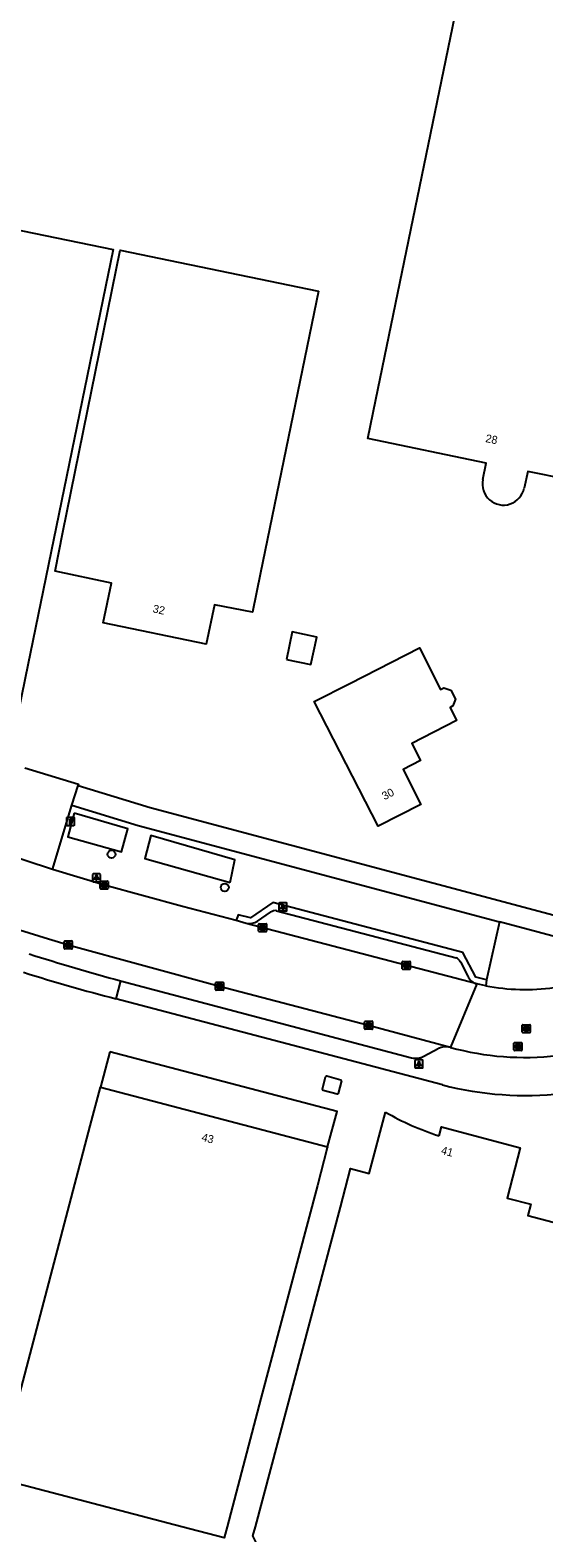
# Model space of a CAD drawing. Extents: x 157692 to 159670, y 381454 to 383289.
# Drawn here: x 158202.3 to 158266.5, y 381749.2 to 381937.1 of the extents above; entities that cross this region are included whole.
import ezdxf

# ---------------------------------------------------------------- set-up
doc = ezdxf.new("R2010")
doc.units = 0
for name, color, linetype in [('IMGEO_Boom', 7, 'Continuous'), ('IMGEO_Groenvoorziening', 7, 'Continuous'), ('IMGEO_Kolk', 7, 'Continuous'), ('IMGEO_Lichtpunt', 7, 'Continuous'), ('IMGEO_Paal', 7, 'Continuous'), ('IMGEO_Pand', 7, 'Continuous'), ('IMGEO_Pand_nummerreeks', 7, 'Continuous'), ('IMGEO_Pand_overbouw', 7, 'Continuous'), ('IMGEO_Rijbaan_lokaal_gesloten', 7, 'Continuous'), ('IMGEO_Rijbaan_lokaal_open', 7, 'Continuous'), ('IMGEO_Rioolput', 7, 'Continuous'), ('IMGEO_Voetpad_open', 7, 'Continuous'), ('IMGEO_Waterloop', 7, 'Continuous')]:
    doc.layers.add(name, color=color, linetype=linetype)

msp = doc.modelspace()

# ---------------------------------------------------------------- linework, layer by layer
at = {"layer": 'IMGEO_Boom'}
for centre in [(158212.48, 381834.06), (158226.62, 381829.91)]:
    msp.add_circle(centre, 0.489, dxfattribs=at)
at = {"layer": 'IMGEO_Groenvoorziening'}
msp.add_lwpolyline([(158260.95, 381825.62), (158259.32, 381818.38)], dxfattribs=at)
at = {"layer": 'IMGEO_Kolk'}
for p, q in [((158211.06, 381829.78), (158211.06, 381830.63)), ((158211.13, 381830.7), (158211.99, 381830.7)), ((158211.55, 381830.48), (158211.57, 381830.48)), ((158212.06, 381830.63), (158212.06, 381829.78)), ((158211.99, 381829.7), (158211.13, 381829.7)), ((158211.57, 381829.92), (158211.54, 381829.92)), ((158230.85, 381824.44), (158230.85, 381825.29)), ((158230.93, 381825.37), (158231.78, 381825.37)), ((158231.34, 381825.15), (158231.36, 381825.15)), ((158231.36, 381824.59), (158231.34, 381824.59)), ((158231.85, 381825.29), (158231.85, 381824.44)), ((158206.57, 381822.3), (158206.57, 381823.15)), ((158206.64, 381823.22), (158207.49, 381823.22)), ((158207.05, 381823), (158207.08, 381823)), ((158207.57, 381823.15), (158207.57, 381822.3)), ((158231.78, 381824.37), (158230.93, 381824.37)), ((158207.49, 381822.22), (158206.64, 381822.22)), ((158207.08, 381822.44), (158207.05, 381822.44)), ((158248.79, 381819.73), (158248.79, 381820.59)), ((158248.87, 381820.66), (158249.72, 381820.66)), ((158249.72, 381819.66), (158248.87, 381819.66)), ((158249.28, 381820.44), (158249.31, 381820.44)), ((158249.3, 381819.88), (158249.28, 381819.88)), ((158249.79, 381820.59), (158249.79, 381819.73)), ((158225.47, 381817.14), (158225.47, 381817.99)), ((158225.55, 381818.06), (158226.4, 381818.06)), ((158226.4, 381817.06), (158225.55, 381817.06)), ((158225.96, 381817.84), (158225.99, 381817.84)), ((158225.98, 381817.28), (158225.96, 381817.28)), ((158226.47, 381817.99), (158226.47, 381817.14)), ((158244.08, 381812.26), (158244.08, 381813.11)), ((158244.15, 381813.19), (158245, 381813.19)), ((158245, 381812.18), (158244.15, 381812.18)), ((158244.59, 381812.41), (158244.56, 381812.41)), ((158244.57, 381812.96), (158244.59, 381812.96)), ((158245.08, 381813.11), (158245.08, 381812.26))]:
    msp.add_line(p, q, dxfattribs=at)
for points in [[(158211.06, 381829.78), (158211.06, 381830.63)], [(158211.13, 381830.7), (158211.99, 381830.7)], [(158211.38, 381830.4), (158211.5, 381830.4), (158211.5, 381830.25), (158211.63, 381830.4), (158211.8, 381830.4), (158211.65, 381830.25), (158211.8, 381830), (158211.65, 381830), (158211.57, 381830.17), (158211.5, 381830.1), (158211.5, 381830), (158211.38, 381830), (158211.38, 381830.4)], [(158212.06, 381830.63), (158212.06, 381829.78)], [(158211.99, 381829.7), (158211.13, 381829.7)], [(158230.85, 381824.44), (158230.85, 381825.29)], [(158230.93, 381825.37), (158231.78, 381825.37)], [(158231.17, 381825.07), (158231.3, 381825.07), (158231.3, 381824.92), (158231.42, 381825.07), (158231.59, 381825.07), (158231.44, 381824.92), (158231.6, 381824.67), (158231.44, 381824.67), (158231.36, 381824.83), (158231.3, 381824.77), (158231.3, 381824.67), (158231.17, 381824.67), (158231.17, 381825.07)], [(158231.85, 381825.29), (158231.85, 381824.44)], [(158206.57, 381822.3), (158206.57, 381823.15)], [(158206.64, 381823.22), (158207.49, 381823.22)], [(158206.89, 381822.92), (158207.01, 381822.92), (158207.01, 381822.77), (158207.14, 381822.92), (158207.3, 381822.92), (158207.16, 381822.77), (158207.31, 381822.52), (158207.16, 381822.52), (158207.07, 381822.69), (158207.01, 381822.62), (158207.01, 381822.52), (158206.89, 381822.52), (158206.89, 381822.92)], [(158207.57, 381823.15), (158207.57, 381822.3)], [(158231.78, 381824.37), (158230.93, 381824.37)], [(158207.49, 381822.22), (158206.64, 381822.22)], [(158248.79, 381819.73), (158248.79, 381820.59)], [(158248.87, 381820.66), (158249.72, 381820.66)], [(158249.72, 381819.66), (158248.87, 381819.66)], [(158249.11, 381820.36), (158249.24, 381820.36), (158249.24, 381820.21), (158249.37, 381820.36), (158249.53, 381820.36), (158249.38, 381820.21), (158249.54, 381819.96), (158249.38, 381819.96), (158249.3, 381820.12), (158249.24, 381820.06), (158249.24, 381819.96), (158249.11, 381819.96), (158249.11, 381820.36)], [(158249.79, 381820.59), (158249.79, 381819.73)], [(158225.47, 381817.14), (158225.47, 381817.99)], [(158225.55, 381818.06), (158226.4, 381818.06)], [(158226.4, 381817.06), (158225.55, 381817.06)], [(158225.79, 381817.76), (158225.92, 381817.76), (158225.92, 381817.61), (158226.05, 381817.76), (158226.21, 381817.76), (158226.07, 381817.61), (158226.22, 381817.36), (158226.07, 381817.36), (158225.98, 381817.53), (158225.92, 381817.46), (158225.92, 381817.36), (158225.79, 381817.36), (158225.79, 381817.76)], [(158226.47, 381817.99), (158226.47, 381817.14)], [(158244.08, 381812.26), (158244.08, 381813.11)], [(158244.15, 381813.19), (158245, 381813.19)], [(158245, 381812.18), (158244.15, 381812.18)], [(158244.4, 381812.88), (158244.52, 381812.88), (158244.52, 381812.73), (158244.65, 381812.88), (158244.82, 381812.88), (158244.67, 381812.73), (158244.82, 381812.48), (158244.67, 381812.48), (158244.59, 381812.65), (158244.52, 381812.58), (158244.52, 381812.48), (158244.4, 381812.48), (158244.4, 381812.88)], [(158245.08, 381813.11), (158245.08, 381812.26)]]:
    msp.add_lwpolyline(points, dxfattribs=at)
for centre, start, end in [((158211.14, 381830.63), 91.552, 178.448), ((158211.14, 381830.63), 91.552, 178.448), ((158211.98, 381830.63), 1.552, 88.448), ((158211.98, 381830.63), 1.552, 88.448), ((158211.14, 381829.78), 181.552, 268.448), ((158211.14, 381829.78), 181.552, 268.448), ((158211.98, 381829.78), 271.552, 358.448), ((158211.98, 381829.78), 271.552, 358.448), ((158230.93, 381825.29), 91.552, 178.448), ((158230.93, 381825.29), 91.552, 178.448), ((158231.78, 381825.29), 1.552, 88.448), ((158231.78, 381825.29), 1.552, 88.448), ((158206.64, 381823.15), 91.552, 178.448), ((158206.64, 381823.15), 91.552, 178.448), ((158207.49, 381823.15), 1.552, 88.448), ((158207.49, 381823.15), 1.552, 88.448), ((158230.93, 381824.44), 181.552, 268.448), ((158230.93, 381824.44), 181.552, 268.448), ((158231.78, 381824.44), 271.552, 358.448), ((158231.78, 381824.44), 271.552, 358.448), ((158206.64, 381822.3), 181.552, 268.448), ((158206.64, 381822.3), 181.552, 268.448), ((158207.49, 381822.3), 271.552, 358.448), ((158207.49, 381822.3), 271.552, 358.448), ((158248.87, 381820.58), 91.552, 178.448), ((158248.87, 381820.58), 91.552, 178.448), ((158248.87, 381819.74), 181.552, 268.448), ((158248.87, 381819.74), 181.552, 268.448), ((158249.72, 381820.58), 1.552, 88.448), ((158249.72, 381820.58), 1.552, 88.448), ((158249.72, 381819.74), 271.552, 358.448), ((158249.72, 381819.74), 271.552, 358.448), ((158225.55, 381817.99), 91.552, 178.448), ((158225.55, 381817.99), 91.552, 178.448), ((158225.55, 381817.14), 181.552, 268.448), ((158225.55, 381817.14), 181.552, 268.448), ((158226.4, 381817.99), 1.552, 88.448), ((158226.4, 381817.99), 1.552, 88.448), ((158226.4, 381817.14), 271.552, 358.448), ((158226.4, 381817.14), 271.552, 358.448), ((158244.15, 381813.11), 91.552, 178.448), ((158244.15, 381813.11), 91.552, 178.448), ((158244.15, 381812.26), 181.552, 268.448), ((158244.15, 381812.26), 181.552, 268.448), ((158245, 381813.11), 1.552, 88.448), ((158245, 381813.11), 1.552, 88.448), ((158245, 381812.26), 271.552, 358.448), ((158245, 381812.26), 271.552, 358.448)]:
    msp.add_arc(centre, 0.0765, start, end, dxfattribs=at)
for centre, major_axis, ratio, start_param, end_param in [((158211.55, 381830.2), (-0.387, 0.002), 0.722429, 4.712389, 7.853982), ((158211.57, 381830.2), (-0.39, 0.002), 0.717154, 1.570796, 4.712389), ((158231.34, 381824.87), (-0.387, 0.002), 0.722429, 4.712389, 7.853982), ((158231.36, 381824.87), (-0.39, 0.002), 0.717154, 1.570796, 4.712389), ((158207.05, 381822.72), (-0.387, 0.002), 0.722429, 4.712389, 7.853982), ((158207.08, 381822.72), (-0.39, 0.002), 0.717154, 1.570796, 4.712389), ((158249.28, 381820.16), (-0.387, 0.002), 0.722429, 4.712389, 7.853982), ((158249.3, 381820.16), (-0.39, 0.002), 0.717154, 1.570796, 4.712389), ((158225.96, 381817.56), (-0.387, 0.002), 0.722429, 4.712389, 7.853982), ((158225.98, 381817.56), (-0.39, 0.002), 0.717154, 1.570796, 4.712389), ((158244.56, 381812.68), (-0.387, 0.002), 0.722429, 4.712389, 7.853982), ((158244.59, 381812.68), (-0.39, 0.002), 0.717154, 1.570796, 4.712389)]:
    msp.add_ellipse(centre, major_axis=major_axis, ratio=ratio, start_param=start_param, end_param=end_param, dxfattribs=at)
at = {"layer": 'IMGEO_Lichtpunt'}
for p, q in [((158210.1, 381831.52), (158210.1, 381830.71)), ((158210.1, 381831.52), (158210.1, 381830.71)), ((158211, 381831.61), (158210.19, 381831.61)), ((158211, 381831.61), (158210.19, 381831.61)), ((158210.19, 381830.62), (158211, 381830.62)), ((158210.19, 381830.62), (158211, 381830.62)), ((158211.1, 381830.71), (158211.1, 381831.52)), ((158211.1, 381830.71), (158211.1, 381831.52)), ((158233.38, 381827.88), (158233.38, 381827.07)), ((158233.38, 381827.88), (158233.38, 381827.07)), ((158234.29, 381827.97), (158233.48, 381827.97)), ((158234.29, 381827.97), (158233.48, 381827.97)), ((158233.48, 381826.98), (158234.29, 381826.98)), ((158233.48, 381826.98), (158234.29, 381826.98)), ((158234.38, 381827.07), (158234.38, 381827.88)), ((158234.38, 381827.07), (158234.38, 381827.88)), ((158250.37, 381808.24), (158250.37, 381807.44)), ((158250.37, 381808.24), (158250.37, 381807.44)), ((158251.27, 381808.34), (158250.46, 381808.34)), ((158251.27, 381808.34), (158250.46, 381808.34)), ((158251.37, 381807.44), (158251.37, 381808.24)), ((158251.37, 381807.44), (158251.37, 381808.24)), ((158250.46, 381807.34), (158251.27, 381807.34)), ((158250.46, 381807.34), (158251.27, 381807.34))]:
    msp.add_line(p, q, dxfattribs=at)
for points in [[(158210.47, 381831.18), (158210.51, 381831.16), (158210.33, 381830.89), (158210.29, 381830.92), (158210.47, 381831.18)], [(158210.58, 381831.14), (158210.62, 381831.14), (158210.62, 381830.81), (158210.58, 381830.81), (158210.58, 381831.14)], [(158210.69, 381831.16), (158210.72, 381831.18), (158210.91, 381830.92), (158210.87, 381830.89), (158210.69, 381831.16)], [(158233.76, 381827.54), (158233.8, 381827.51), (158233.61, 381827.25), (158233.57, 381827.28), (158233.76, 381827.54)], [(158233.86, 381827.49), (158233.91, 381827.49), (158233.91, 381827.17), (158233.86, 381827.17), (158233.86, 381827.49)], [(158233.97, 381827.51), (158234.01, 381827.54), (158234.19, 381827.28), (158234.16, 381827.25), (158233.97, 381827.51)], [(158250.74, 381807.91), (158250.78, 381807.88), (158250.59, 381807.62), (158250.56, 381807.64), (158250.74, 381807.91)], [(158250.84, 381807.86), (158250.89, 381807.86), (158250.89, 381807.54), (158250.84, 381807.54), (158250.84, 381807.86)], [(158250.95, 381807.88), (158250.99, 381807.91), (158251.18, 381807.64), (158251.14, 381807.62), (158250.95, 381807.88)]]:
    msp.add_lwpolyline(points, dxfattribs=at)
for centre in [(158210.6, 381831.32), (158233.88, 381827.68), (158250.87, 381808.04)]:
    msp.add_circle(centre, 0.0994, dxfattribs=at)
for centre, start, end in [((158210.19, 381831.52), 90, 180), ((158210.19, 381831.52), 90, 180), ((158210.19, 381830.71), 180, 270), ((158210.19, 381830.71), 180, 270), ((158211, 381831.52), 0, 90), ((158211, 381831.52), 0, 90), ((158211, 381830.71), 270, 0), ((158211, 381830.71), 270, 360), ((158233.48, 381827.88), 90, 180), ((158233.48, 381827.88), 90, 180), ((158233.48, 381827.07), 180, 270), ((158233.48, 381827.07), 180, 270), ((158234.29, 381827.88), 0, 90), ((158234.29, 381827.88), 0, 90), ((158234.29, 381827.07), 270, 0), ((158234.29, 381827.07), 270, 360), ((158250.46, 381808.24), 90, 180), ((158250.46, 381808.24), 90, 180), ((158251.27, 381808.24), 0, 90), ((158251.27, 381808.24), 0, 90), ((158250.46, 381807.44), 180, 270), ((158250.46, 381807.44), 180, 270), ((158251.27, 381807.44), 270, 0), ((158251.27, 381807.44), 270, 360)]:
    msp.add_arc(centre, 0.0946, start, end, dxfattribs=at)
at = {"layer": 'IMGEO_Paal'}
for p, q in [((158206.87, 381838.56), (158206.87, 381837.72)), ((158206.87, 381838.56), (158206.87, 381837.72)), ((158207.78, 381838.65), (158206.94, 381838.65)), ((158207.78, 381838.65), (158206.94, 381838.65)), ((158206.95, 381837.65), (158207.79, 381837.65)), ((158206.95, 381837.65), (158207.79, 381837.65)), ((158207.86, 381837.73), (158207.86, 381838.57)), ((158207.86, 381837.73), (158207.86, 381838.57))]:
    msp.add_line(p, q, dxfattribs=at)
msp.add_lwpolyline([(158207.28, 381838.46), (158207.44, 381838.46), (158207.44, 381837.73), (158207.28, 381837.73), (158207.28, 381838.46)], dxfattribs=at)
for centre, start, end in [((158206.94, 381838.57), 92.4484, 184.2845), ((158206.94, 381838.57), 92.4484, 184.2845), ((158206.94, 381837.73), 182.4484, 274.2845), ((158206.94, 381837.73), 182.4484, 274.2845), ((158207.79, 381838.57), 2.4484, 94.2845), ((158207.79, 381838.57), 2.4484, 94.2845), ((158207.79, 381837.73), 272.4484, 4.2845), ((158207.79, 381837.73), 272.4484, 4.2845)]:
    msp.add_arc(centre, 0.0779, start, end, dxfattribs=at)
at = {"layer": 'IMGEO_Pand'}
for points in [[(158258.87, 381880.89), (158259.27, 381882.93), (158244.48, 381886.01), (158245.49, 381890.91), (158267.95, 382000), (158270, 382009.98), (158291.58, 382005.49), (158291.55, 382005.38)], [(158289.44, 381995.23), (158283.22, 381965.39), (158306.23, 381960.62), (158300.57, 381933.24), (158280.97, 381937.29), (158275.48, 381910.38), (158273.57, 381900.89), (158271.56, 381891.25), (158274.06, 381890.71), (158276.45, 381890.19), (158275.35, 381884.81), (158274.36, 381879.91), (158264.45, 381881.89), (158264, 381879.82)], [(158136.17, 381925.26), (158192.83, 381913.72), (158212.68, 381909.65), (158201.7, 381856.05), (158200.69, 381851.15), (158200.05, 381851.25), (158200.81, 381854.95), (158186.49, 381857.9), (158187.18, 381862.85), (158191.44, 381893.33), (158184.12, 381894.82), (158154.7, 381900.8), (158150.09, 381901.74)], [(158238.32, 381904.43), (158231.09, 381869.22), (158230.08, 381864.32), (158225.32, 381865.25), (158224.3, 381860.33), (158211.44, 381862.98), (158212.49, 381867.94), (158205.42, 381869.42), (158206.41, 381874.32), (158213.56, 381909.55), (158238.32, 381904.43)], [(158234.31, 381858.39), (158237.39, 381857.76), (158238.1, 381861.2), (158235.02, 381861.84), (158234.31, 381858.39)], [(158254.85, 381854.57), (158255.42, 381853.45), (158255.11, 381852.6), (158254.75, 381852.41), (158255.58, 381850.77), (158249.98, 381847.89), (158251.05, 381845.76), (158248.89, 381844.65), (158251.12, 381840.29), (158245.77, 381837.57), (158237.79, 381853.14), (158242.24, 381855.41), (158250.92, 381859.85), (158253.58, 381854.66), (158253.98, 381854.85), (158254.85, 381854.57)], [(158239.21, 381806.25), (158239.35, 381806.34), (158241.11, 381805.87), (158241.18, 381805.73), (158240.78, 381804.17), (158240.64, 381804.09), (158238.9, 381804.54), (158238.82, 381804.69), (158239.21, 381806.25)], [(158209.83, 381800.12), (158211.1, 381804.95), (158239.47, 381797.49), (158239.43, 381797.36), (158238.19, 381792.67), (158231.14, 381766.02), (158226.9, 381750), (158226.53, 381748.62), (158221.26, 381750), (158198.19, 381756.03), (158209.83, 381800.12)], [(158248.58, 381711.93), (158242.38, 381724.36), (158230.14, 381748.88), (158230.44, 381750), (158241.06, 381789.93), (158242.34, 381794.76), (158244.64, 381794.17), (158246.68, 381801.84)], [(158253.38, 381798.87), (158253.67, 381799.97), (158263.5, 381797.38), (158261.87, 381791.09), (158264.85, 381790.32), (158264.48, 381788.92), (158272.55, 381786.79)]]:
    msp.add_lwpolyline(points, dxfattribs=at)
for centre, radius, start, end in [((158261.43, 381880.32), 2.62, 167.6579, 348.8349), ((158263.86, 381831.49), 34.27, 239.9197, 252.1919)]:
    msp.add_arc(centre, radius, start, end, dxfattribs=at)
at = {"layer": 'IMGEO_Pand_overbouw'}
msp.add_lwpolyline([(158212.27, 381809.36), (158211.1, 381804.95), (158239.47, 381797.49), (158240.64, 381801.91)], close=True, dxfattribs=at)
at = {"layer": 'IMGEO_Rijbaan_lokaal_gesloten'}
for points in [[(158205.12, 381832.15), (158198.37, 381834.36)], [(158228.06, 381825.76), (158221.36, 381827.53), (158211.58, 381830.2), (158205.12, 381832.15)], [(158229.31, 381825.42), (158228.06, 381825.76)], [(158258.12, 381817.84), (158229.31, 381825.42)], [(158207.07, 381822.73), (158225.97, 381817.57), (158244.58, 381812.69), (158254.8, 381809.93)], [(158258.12, 381817.84), (158254.8, 381809.93)], [(158259.21, 381817.61), (158258.12, 381817.84)]]:
    msp.add_lwpolyline(points, dxfattribs=at)
for centre, radius, start, end in [((158293.53, 382111.81), 301.73, 245.5859, 253.3476), ((158264.17, 381844.19), 27.04, 259.4383, 277.5776), ((158264.15, 381843.95), 35.29, 254.6277, 298.2751)]:
    msp.add_arc(centre, radius, start, end, dxfattribs=at)
at = {"layer": 'IMGEO_Rijbaan_lokaal_open'}
for points in [[(158201.64, 381844.86), (158208.36, 381842.81), (158208.31, 381842.63)], [(158207.53, 381840.18), (158208.31, 381842.63)], [(158205.12, 381832.15), (158207.53, 381840.18)]]:
    msp.add_lwpolyline(points, dxfattribs=at)
at = {"layer": 'IMGEO_Rioolput'}
for p, q in [((158263.78, 381811.82), (158263.78, 381812.68)), ((158263.85, 381812.75), (158264.71, 381812.75)), ((158264.71, 381811.75), (158263.85, 381811.75)), ((158264.29, 381811.97), (158264.26, 381811.97)), ((158264.27, 381812.53), (158264.29, 381812.53)), ((158264.78, 381812.68), (158264.78, 381811.82)), ((158262.74, 381809.59), (158262.74, 381810.44)), ((158262.81, 381810.52), (158263.67, 381810.52)), ((158263.67, 381809.52), (158262.81, 381809.52)), ((158263.23, 381810.3), (158263.25, 381810.3)), ((158263.25, 381809.74), (158263.23, 381809.74)), ((158263.74, 381810.44), (158263.74, 381809.59))]:
    msp.add_line(p, q, dxfattribs=at)
for points in [[(158263.78, 381811.82), (158263.78, 381812.68)], [(158263.85, 381812.75), (158264.71, 381812.75)], [(158264.71, 381811.75), (158263.85, 381811.75)], [(158264.37, 381812.45), (158264.11, 381812.45), (158264.11, 381812.05)], [(158264.11, 381812.05), (158264.24, 381812.05), (158264.24, 381812.21), (158264.25, 381812.21)], [(158264.29, 381812.37), (158264.24, 381812.37), (158264.24, 381812.29)], [(158264.24, 381812.29), (158264.29, 381812.29)], [(158264.3, 381812.18), (158264.37, 381812.05), (158264.51, 381812.05), (158264.44, 381812.18)], [(158264.78, 381812.68), (158264.78, 381811.82)], [(158262.74, 381809.59), (158262.74, 381810.44)], [(158262.81, 381810.52), (158263.67, 381810.52)], [(158263.67, 381809.52), (158262.81, 381809.52)], [(158263.33, 381810.22), (158263.08, 381810.22), (158263.08, 381809.82)], [(158263.08, 381809.82), (158263.2, 381809.82), (158263.2, 381809.98), (158263.21, 381809.98)], [(158263.26, 381810.14), (158263.2, 381810.14), (158263.2, 381810.06)], [(158263.2, 381810.06), (158263.25, 381810.06)], [(158263.26, 381809.95), (158263.33, 381809.82), (158263.47, 381809.82), (158263.4, 381809.94)], [(158263.74, 381810.44), (158263.74, 381809.59)]]:
    msp.add_lwpolyline(points, dxfattribs=at)
for centre, radius, start, end in [((158263.85, 381812.67), 0.0765, 91.552, 178.448), ((158263.85, 381812.67), 0.0765, 91.552, 178.448), ((158263.85, 381811.83), 0.0765, 181.552, 268.448), ((158263.85, 381811.83), 0.0765, 181.552, 268.448), ((158264.25, 381812.16), 0.0533, 26.0293, 88.6989), ((158264.3, 381812.27), 0.0964, 77.0061, 93.1865), ((158264.28, 381812.48), 0.19, 274.7715, 282.9687), ((158264.31, 381812.33), 0.0378, 276.6634, 79.6772), ((158264.37, 381812.34), 0.109, 350.3612, 89.416), ((158264.36, 381812.34), 0.112, 277.5842, 350.9817), ((158264.35, 381812.12), 0.108, 29.5134, 73.7905), ((158264.7, 381812.67), 0.0765, 1.552, 88.448), ((158264.7, 381812.67), 0.0765, 1.552, 88.448), ((158264.7, 381811.83), 0.0765, 271.552, 358.448), ((158264.7, 381811.83), 0.0765, 271.552, 358.448), ((158262.82, 381810.44), 0.0765, 91.552, 178.448), ((158262.82, 381810.44), 0.0765, 91.552, 178.448), ((158262.82, 381809.59), 0.0765, 181.552, 268.448), ((158262.82, 381809.59), 0.0765, 181.552, 268.448), ((158263.21, 381809.93), 0.0533, 26.0293, 88.6989), ((158263.24, 381810.25), 0.19, 274.7715, 282.9687), ((158263.26, 381810.04), 0.0964, 77.0061, 93.1865), ((158263.28, 381810.1), 0.0378, 276.6634, 79.6772), ((158263.33, 381810.11), 0.109, 350.3612, 89.416), ((158263.33, 381810.11), 0.112, 277.5842, 350.9817), ((158263.31, 381809.89), 0.108, 29.5134, 73.7905), ((158263.66, 381810.44), 0.0765, 1.552, 88.448), ((158263.66, 381810.44), 0.0765, 1.552, 88.448), ((158263.66, 381809.59), 0.0765, 271.552, 358.448), ((158263.66, 381809.59), 0.0765, 271.552, 358.448)]:
    msp.add_arc(centre, radius, start, end, dxfattribs=at)
for centre, major_axis, ratio, start_param, end_param in [((158264.27, 381812.25), (-0.387, 0.002), 0.722429, 4.712389, 7.853982), ((158264.29, 381812.25), (-0.39, 0.002), 0.717154, 1.570796, 4.712389), ((158263.23, 381810.02), (-0.387, 0.002), 0.722429, 4.712389, 7.853982), ((158263.25, 381810.02), (-0.39, 0.002), 0.717154, 1.570796, 4.712389)]:
    msp.add_ellipse(centre, major_axis=major_axis, ratio=ratio, start_param=start_param, end_param=end_param, dxfattribs=at)
at = {"layer": 'IMGEO_Voetpad_open'}
for points in [[(158208.31, 381842.63), (158217.32, 381839.91), (158270.26, 381825.79), (158286.56, 381834.29)], [(158207.53, 381840.18), (158215.81, 381837.66), (158260.95, 381825.62)], [(158287.73, 381832.03), (158271.46, 381823.49), (158270.61, 381823.04), (158260.95, 381825.62)], [(158259.32, 381818.38), (158257.96, 381818.7), (158256.36, 381821.76), (158232.63, 381828.02), (158229.85, 381826.12), (158228.29, 381826.5), (158228.06, 381825.76)], [(158230.7, 381825.71), (158232.35, 381826.81)], [(158233.1, 381827), (158255.51, 381821.12)], [(158256.06, 381820.59), (158256.98, 381818.8)], [(158213.61, 381818.22), (158213.03, 381816)], [(158213.61, 381818.22), (158249.96, 381808.63)], [(158259.32, 381818.38), (158259.21, 381817.61)], [(158253.82, 381805.24), (158243.86, 381807.85), (158213.03, 381816)], [(158251.48, 381808.83), (158253.27, 381809.76)]]:
    msp.add_lwpolyline(points, dxfattribs=at)
for centre, radius, start, end in [((158232.99, 381825.87), 1.14, 84.2451, 124.114), ((158229.68, 381827.15), 1.76, 257.8322, 305.2161), ((158302.43, 382140.08), 333.88, 252.5289, 254.5737), ((158254.88, 381819.92), 1.36, 29.3521, 62.2291), ((158265.96, 382022.65), 213.32, 252.4067, 255.6357), ((158258.61, 381819.58), 1.81, 205.3811, 254.0741), ((158254.26, 381807.76), 2.23, 76.0113, 116.4309), ((158250.47, 381810.59), 2.03, 255.3677, 299.8364), ((158264.15, 381844.93), 41.02, 255.414, 297.495)]:
    msp.add_arc(centre, radius, start, end, dxfattribs=at)
at = {"layer": 'IMGEO_Waterloop'}
for points in [[(158207.82, 381839.18), (158207.01, 381836.24), (158213.74, 381834.34), (158214.51, 381837.24), (158207.82, 381839.18)], [(158227.28, 381830.51), (158227.87, 381833.36), (158217.4, 381836.4), (158216.63, 381833.52), (158227.28, 381830.51)]]:
    msp.add_lwpolyline(points, dxfattribs=at)

# ---------------------------------------------------------------- texts
at = {"layer": 'IMGEO_Pand_nummerreeks'}
for s, rotation, p in [('28', 348.4434, (158259.12, 381885.59)), ('32', 348.3666, (158217.57, 381864.29)), ('30', 26.9875, (158246.56, 381840.8)), ('43', 345.2673, (158223.65, 381798.26)), ('41', 345.1324, (158253.56, 381796.62))]:
    msp.add_text(s, height=1, rotation=rotation, dxfattribs=at).set_placement(p)

doc.saveas('drawing.dxf')
